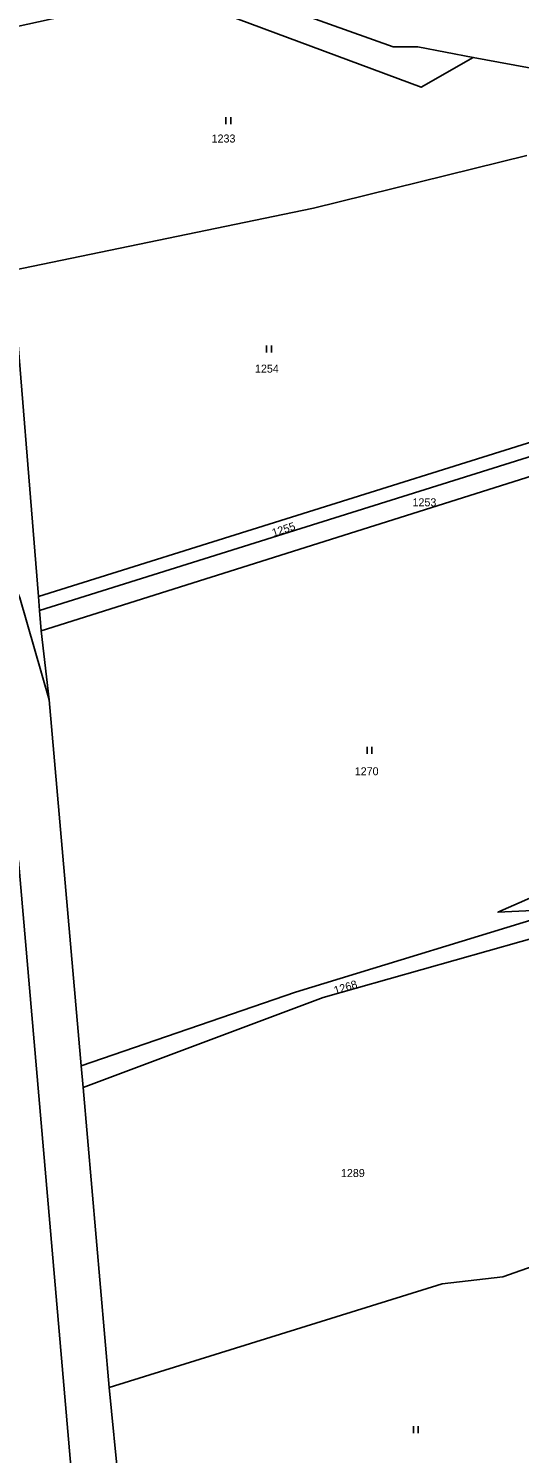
# Model space of a CAD drawing. Extents: x -520431 to -517205, y -1075927 to -1074013.
# Drawn here: x -518108.8 to -518004.6, y -1075007.9 to -1074705.2 of the extents above; entities that cross this region are included whole.
import ezdxf

# ---------------------------------------------------------------- set-up
doc = ezdxf.new("R2010")
doc.units = 0
for name, color, linetype in [('Hranice parcel', 7, 'Continuous'), ('Parcelní čísla', 7, 'Continuous'), ('Vrstva 54', 7, 'Continuous'), ('Značky kultur', 7, 'Continuous')]:
    doc.layers.add(name, color=color, linetype=linetype)

msp = doc.modelspace()

# ---------------------------------------------------------------- linework, layer by layer
at = {"layer": 'Hranice parcel'}
for p, q in [((-518106.73, -1074825.85), (-518112.33, -1074756.64)), ((-518106.49, -1074828.84), (-518106.73, -1074825.85)), ((-518106.14, -1074833.17), (-518106.49, -1074828.84)), ((-518104.44, -1074847.81), (-518106.14, -1074833.17)), ((-518097.66, -1074925.58), (-518104.44, -1074847.81)), ((-518110.95, -1074881.98), (-518094.89, -1075068.19)), ((-518097.66, -1074925.58), (-518097.26, -1074930.14)), ((-518097.26, -1074930.14), (-518091.7, -1074993.89)), ((-518082.67, -1075086.62), (-518091.7, -1074993.89))]:
    msp.add_line(p, q, dxfattribs=at)
for points in [[(-518154.63, -1074686.06), (-518105.93, -1074694.68), (-518098.95, -1074693.08), (-518079.14, -1074694.38), (-518059.45, -1074699.07), (-518031.37, -1074709.15), (-518026.16, -1074709.16), (-518014.4, -1074711.36)], [(-518114.15, -1074705.43), (-518086.04, -1074699.31), (-518066.82, -1074702.32), (-518025.45, -1074717.72), (-518014.4, -1074711.36)], [(-518014.4, -1074711.36), (-518000.17, -1074714.03), (-517977.41, -1074721.51), (-517974.6, -1074722.09)], [(-518112.33, -1074756.64), (-518048.28, -1074743.37), (-518002.99, -1074732.19)], [(-518106.73, -1074825.85), (-517999.22, -1074792.16), (-517989.81, -1074784.46)], [(-517987.79, -1074795.75), (-518000.42, -1074795.58), (-518106.49, -1074828.84)], [(-518106.14, -1074833.17), (-517999.16, -1074799.39), (-517981.14, -1074801.25), (-517975.04, -1074798.6)], [(-518114.84, -1074816.24), (-518110.7, -1074826.14), (-518104.44, -1074847.81)], [(-517979.25, -1074880.04), (-517988.61, -1074883.92), (-518009.15, -1074892.96), (-517994.32, -1074892.2)], [(-517994.32, -1074892.2), (-518052.15, -1074909.94), (-518097.66, -1074925.58)], [(-518097.26, -1074930.14), (-518046.24, -1074911.04), (-517976.15, -1074891.26)], [(-518091.7, -1074993.89), (-518020.99, -1074971.84), (-518008.1, -1074970.4), (-517978.75, -1074960.03), (-517955.54, -1074945.96)]]:
    msp.add_lwpolyline(points, dxfattribs=at)
at = {"layer": 'Vrstva 54'}
msp.add_lwpolyline([(-518000.17, -1074714.03), (-518014.4, -1074711.36), (-518026.16, -1074709.16), (-518031.37, -1074709.15), (-518059.45, -1074699.07)], dxfattribs=at)
at = {"layer": 'Značky kultur'}
for p, q in [((-518066.9, -1074725.57), (-518066.9, -1074724.07)), ((-518065.9, -1074725.57), (-518065.9, -1074724.07)), ((-518058.26, -1074774.08), (-518058.26, -1074772.58)), ((-518057.26, -1074774.08), (-518057.26, -1074772.58)), ((-518036.93, -1074859.3), (-518036.93, -1074857.8)), ((-518035.93, -1074859.3), (-518035.93, -1074857.8)), ((-518027.07, -1075003.59), (-518027.07, -1075002.09)), ((-518026.07, -1075003.59), (-518026.07, -1075002.09))]:
    msp.add_line(p, q, dxfattribs=at)

# ---------------------------------------------------------------- texts
at = {"layer": 'Parcelní čísla'}
for s, p in [('1233', (-518069.95, -1074729.45)), ('1254', (-518060.74, -1074778.33)), ('1253', (-518027.28, -1074806.72)), ('1270', (-518039.55, -1074863.85)), ('1289', (-518042.48, -1074949.19))]:
    msp.add_text(s, height=1.7, dxfattribs=at).set_placement(p)
for s, rotation, p in [('1255', 18, (-518056.82, -1074813.21)), ('1268', 17, (-518043.69, -1074910.42))]:
    msp.add_text(s, height=1.7, rotation=rotation, dxfattribs=at).set_placement(p)

doc.saveas('drawing.dxf')
